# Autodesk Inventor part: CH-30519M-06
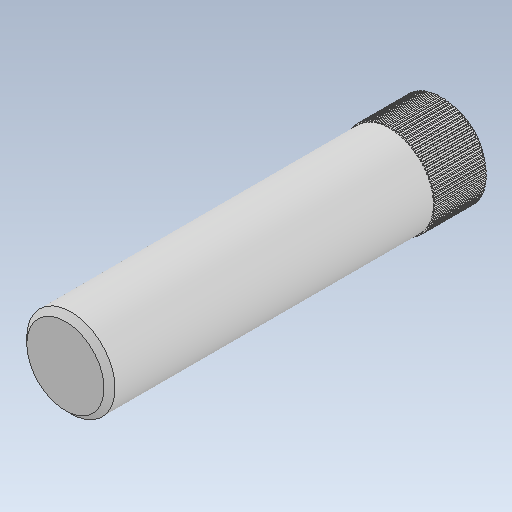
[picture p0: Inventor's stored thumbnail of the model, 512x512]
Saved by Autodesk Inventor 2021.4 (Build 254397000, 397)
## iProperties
Created: 2017-11
Part Number: CH-30519M-06
Material: Ogólny
Document SubType Name: Modeling
Designer: user
Density: 1 g/cm^3
Appearance: Domyślna
Author: user
Revision Number: ÈÎºÎ
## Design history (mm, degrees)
feature "ÕóÁÐ(Ô²ÖÜ)1"
node "Bryła1"
